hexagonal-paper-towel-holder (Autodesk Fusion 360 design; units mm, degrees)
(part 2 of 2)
sketch "Sketch2" plane through (0, 0, 5) normal (0, 0, 1) x axis (-1, 0, 0)
  line L1 (-30.6175, -23.5714) -> (-24.844, -23.5714)
  line L2 (-33.5043, -18.5714) -> (-30.6175, -23.5714)
  line L3 (-30.6175, -13.5714) -> (-33.5043, -18.5714)
  line L4 (-24.844, -13.5714) -> (-30.6175, -13.5714)
  line L5 (-21.9573, -18.5714) -> (-24.844, -13.5714)
  line L6 (-24.844, -23.5714) -> (-21.9573, -18.5714)
  line L7 (-97.4252, -100.7143) -> (-91.6517, -100.7143)
  line L8 (-100.312, -95.7143) -> (-97.4252, -100.7143)
  line L9 (-97.4252, -90.7143) -> (-100.312, -95.7143)
  line L10 (-91.6517, -90.7143) -> (-97.4252, -90.7143)
  line L11 (-88.7649, -95.7143) -> (-91.6517, -90.7143)
  line L12 (-91.6517, -100.7143) -> (-88.7649, -95.7143)
  line L13 (-36.4555, -97.1429) -> (-41.7521, -97.1429)
  line L14 (-39.2598, -102) -> (-36.4555, -97.1429)
  line L15 (-44.5564, -102) -> (-39.2598, -102)
  line L16 (-41.7521, -97.1429) -> (-44.5564, -102)
  line L17 (-55.4436, -102) -> (-58.2479, -97.1429)
  line L18 (-66.8256, -102) -> (-55.4436, -102)
  line L19 (-64.0214, -97.1429) -> (-66.8256, -102)
  line L20 (-58.2479, -97.1429) -> (-64.0214, -97.1429)
  line L21 (-77.7128, -102) -> (-80.5171, -97.1429)
  line L22 (-89.0949, -102) -> (-77.7128, -102)
  line L23 (-86.2906, -97.1429) -> (-89.0949, -102)
  line L24 (-80.5171, -97.1429) -> (-86.2906, -97.1429)
  line L25 (-99.982, -102) -> (-102.7863, -97.1429)
  line L26 (-110.9553, -102) -> (-99.982, -102)
  line L27 (-106.7432, -97.1429) -> (-110.9553, -102)
  line L28 (-102.7863, -97.1429) -> (-106.7432, -97.1429)
  line L29 (-104.2655, -94.2857) -> (-102.7863, -94.2857)
  line L30 (-99.9116, -89.2649) -> (-104.2655, -94.2857)
  line L31 (-99.8996, -89.2857) -> (-99.9116, -89.2649)
  line L32 (-102.7863, -94.2857) -> (-99.8996, -89.2857)
  line L33 (-97.931, -86.9811) -> (-97.4252, -87.8571)
  line L34 (-90.9991, -78.9875) -> (-97.931, -86.9811)
  line L35 (-88.7649, -82.8571) -> (-90.9991, -78.9875)
  line L36 (-91.6517, -87.8571) -> (-88.7649, -82.8571)
  line L37 (-97.4252, -87.8571) -> (-91.6517, -87.8571)
  line L38 (-89.0185, -76.7036) -> (-86.2906, -81.4286)
  line L39 (-84.444, -71.4286) -> (-89.0185, -76.7036)
  line L40 (-80.5171, -71.4286) -> (-84.444, -71.4286)
  line L41 (-77.6303, -76.4286) -> (-80.5171, -71.4286)
  line L42 (-80.5171, -81.4286) -> (-77.6303, -76.4286)
  line L43 (-86.2906, -81.4286) -> (-80.5171, -81.4286)
  line L44 (-25.3209, -77.8571) -> (-30.6175, -77.8571)
  line L45 (-30.856, -87.4441) -> (-25.3209, -77.8571)
  line L46 (-33.5043, -82.8571) -> (-30.856, -87.4441)
  line L47 (-30.6175, -77.8571) -> (-33.5043, -82.8571)
  line L48 (-14.1863, -58.5714) -> (-19.4829, -58.5714)
  line L49 (-19.7214, -68.1584) -> (-14.1863, -58.5714)
  line L50 (-22.3697, -63.5714) -> (-19.7214, -68.1584)
  line L51 (-19.4829, -58.5714) -> (-22.3697, -63.5714)
  line L52 (-86.2906, -94.2857) -> (-80.5171, -94.2857)
  line L53 (-89.1773, -89.2857) -> (-86.2906, -94.2857)
  line L54 (-86.2906, -84.2857) -> (-89.1773, -89.2857)
  line L55 (-80.5171, -84.2857) -> (-86.2906, -84.2857)
  line L56 (-77.6303, -89.2857) -> (-80.5171, -84.2857)
  line L57 (-80.5171, -94.2857) -> (-77.6303, -89.2857)
  line L58 (-75.156, -100.7143) -> (-69.3825, -100.7143)
  line L59 (-78.0427, -95.7143) -> (-75.156, -100.7143)
  line L60 (-75.156, -90.7143) -> (-78.0427, -95.7143)
  line L61 (-69.3825, -90.7143) -> (-75.156, -90.7143)
  line L62 (-66.4957, -95.7143) -> (-69.3825, -90.7143)
  line L63 (-69.3825, -100.7143) -> (-66.4957, -95.7143)
  line L64 (-75.156, -87.8571) -> (-69.3825, -87.8571)
  line L65 (-78.0427, -82.8571) -> (-75.156, -87.8571)
  line L66 (-75.156, -77.8571) -> (-78.0427, -82.8571)
  line L67 (-69.3825, -77.8571) -> (-75.156, -77.8571)
  line L68 (-66.4957, -82.8571) -> (-69.3825, -77.8571)
  line L69 (-69.3825, -87.8571) -> (-66.4957, -82.8571)
  line L70 (-64.0214, -94.2857) -> (-58.2479, -94.2857)
  line L71 (-66.9081, -89.2857) -> (-64.0214, -94.2857)
  line L72 (-64.0214, -84.2857) -> (-66.9081, -89.2857)
  line L73 (-58.2479, -84.2857) -> (-64.0214, -84.2857)
  line L74 (-55.3611, -89.2857) -> (-58.2479, -84.2857)
  line L75 (-58.2479, -94.2857) -> (-55.3611, -89.2857)
  line L76 (-52.8868, -100.7143) -> (-47.1132, -100.7143)
  line L77 (-55.7735, -95.7143) -> (-52.8868, -100.7143)
  line L78 (-52.8868, -90.7143) -> (-55.7735, -95.7143)
  line L79 (-47.1132, -90.7143) -> (-52.8868, -90.7143)
  line L80 (-44.2265, -95.7143) -> (-47.1132, -90.7143)
  line L81 (-47.1132, -100.7143) -> (-44.2265, -95.7143)
  line L82 (-75.156, -75) -> (-69.3825, -75)
  line L83 (-78.0427, -70) -> (-75.156, -75)
  line L84 (-75.156, -65) -> (-78.0427, -70)
  line L85 (-69.3825, -65) -> (-75.156, -65)
  line L86 (-66.4957, -70) -> (-69.3825, -65)
  line L87 (-69.3825, -75) -> (-66.4957, -70)
  line L88 (-64.0214, -81.4286) -> (-58.2479, -81.4286)
  line L89 (-66.9081, -76.4286) -> (-64.0214, -81.4286)
  line L90 (-64.0214, -71.4286) -> (-66.9081, -76.4286)
  line L91 (-58.2479, -71.4286) -> (-64.0214, -71.4286)
  line L92 (-55.3611, -76.4286) -> (-58.2479, -71.4286)
  line L93 (-58.2479, -81.4286) -> (-55.3611, -76.4286)
  line L94 (-52.8868, -87.8571) -> (-47.1132, -87.8571)
  line L95 (-55.7735, -82.8571) -> (-52.8868, -87.8571)
  line L96 (-52.8868, -77.8571) -> (-55.7735, -82.8571)
  line L97 (-47.1132, -77.8571) -> (-52.8868, -77.8571)
  line L98 (-44.2265, -82.8571) -> (-47.1132, -77.8571)
  line L99 (-47.1132, -87.8571) -> (-44.2265, -82.8571)
  line L100 (-41.7521, -94.2857) -> (-35.9786, -94.2857)
  line L101 (-44.6389, -89.2857) -> (-41.7521, -94.2857)
  line L102 (-41.7521, -84.2857) -> (-44.6389, -89.2857)
  line L103 (-35.9786, -84.2857) -> (-41.7521, -84.2857)
  line L104 (-33.0919, -89.2857) -> (-35.9786, -84.2857)
  line L105 (-35.9786, -94.2857) -> (-33.0919, -89.2857)
  line L106 (-64.0214, -68.5714) -> (-58.2479, -68.5714)
  line L107 (-66.9081, -63.5714) -> (-64.0214, -68.5714)
  line L108 (-64.0214, -58.5714) -> (-66.9081, -63.5714)
  line L109 (-58.2479, -58.5714) -> (-64.0214, -58.5714)
  line L110 (-55.3611, -63.5714) -> (-58.2479, -58.5714)
  line L111 (-58.2479, -68.5714) -> (-55.3611, -63.5714)
  line L112 (-41.7521, -81.4286) -> (-35.9786, -81.4286)
  line L113 (-44.6389, -76.4286) -> (-41.7521, -81.4286)
  line L114 (-41.7521, -71.4286) -> (-44.6389, -76.4286)
  line L115 (-35.9786, -71.4286) -> (-41.7521, -71.4286)
  line L116 (-33.0919, -76.4286) -> (-35.9786, -71.4286)
  line L117 (-35.9786, -81.4286) -> (-33.0919, -76.4286)
  line L118 (-52.8868, -62.1429) -> (-47.1132, -62.1429)
  line L119 (-55.7735, -57.1429) -> (-52.8868, -62.1429)
  line L120 (-52.8868, -52.1429) -> (-55.7735, -57.1429)
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  point P28 (-110.9553, -102)
  point P274 (-110.9553, -102)
  coincident P28 P274
extrude "Extrude2" add sketch "Sketch2" along normal blind 17 named "d15_1_1"
extrude "Extrude3" add sketch "Sketch2" along normal blind 30 named "d17_1_1"
sketch "Sketch3" plane through (-17.3205, 10, 0) normal (-0.866, 0.5, 0) x axis (-0.5, -0.866, 0)
  line L1 (0, 0) -> (-109.6966, 0)
  line L2 (0, 5) -> (0, 0)
  line L3 (-106.2324, 5) -> (0, 5)
  line L4 (-106.2324, 35) -> (-106.2324, 5)
  line L5 (-109.6966, 35) -> (-106.2324, 35)
  line L6 (-109.6966, 0) -> (-109.6966, 35)
  line L7 (-91.618, 35) -> (-106.2324, 35)
  line L8 (-94.1706, 0) -> (-109.6966, 0)
  line L9 (-106.2324, 35) -> (-94.1706, 0)
  point P6 (-106.2324, 35)
  point P8 (-106.2324, 35)
  point P10 (-94.1706, 0)
  point P2 (-109.6966, 0)
  point P11 (-109.6966, 0)
  point P12 (-106.2324, 35)
  horizontal L7
  coincident P6 P8
  coincident L1 P10
  coincident P2 P11
  coincident P6 P12
  dimension "d73_1" distance P10 P11 = 15.526
extrude "Extrude4" add sketch "Sketch3" profile of L1 L3 L4 L5 L6 against normal blind 3 named "d20_1_1"
sketch "Sketch4" plane through (15.1099, -13.1031, 0) normal (0.7555, -0.6552, 0) x axis (0.6552, 0.7555, 0)
  line L1 (156.3259, 0) -> (0, 0)
  line L2 (156.3259, 35) -> (156.3259, 0)
  line L3 (152.3549, 35) -> (156.3259, 35)
  line L4 (152.3549, 5) -> (152.3549, 35)
  line L5 (0, 5) -> (152.3549, 5)
  line L6 (0, 0) -> (0, 5)
  line L7 (168.6241, 35) -> (152.3549, 35)
  line L8 (140.7999, 0) -> (156.3259, 0)
  line L9 (152.3549, 35) -> (140.7999, 0)
  point P5 (152.3549, 35)
  point P8 (152.3549, 35)
  point P3 (156.3259, 0)
  point P10 (156.3259, 0)
  point P11 (140.7999, 0)
  horizontal L7
  coincident P5 P8
  coincident P3 P10
  perpendicular L2 L8
  dimension "d74_1" distance P10 P11 = 15.526
extrude "Extrude5" add sketch "Sketch4" profile of L4 L5 L9 against normal blind 3 named "d23_1_1"
work_plane "WorkPlane1" RotateAngle 90
sketch "Sketch7" plane through (37.5278, 105, 17.5) normal (-1, 0, 0) x axis (0, 1, 0)
  line L1 (0, -17.5) -> (0, 17.5)
  line L2 (20.5, -17.5) -> (0, -17.5)
  line L3 (20.5, 17.5) -> (20.5, -17.5)
  line L4 (0, 17.5) -> (20.5, 17.5)
  line L5 (0, -17.5) -> (0, 17.5)
  point P3 (0, -17.5)
  point P4 (0, -17.5)
  point P5 (20.5, -17.5)
  horizontal L2
  vertical L3
  horizontal L4
  vertical L5
  coincident P3 P4
  dimension "d76" distance P4 P5 = 20.5
extrude "Extrude8" add sketch "Sketch7" against normal blind 3
sketch "Sketch8" plane through (0, 125.5, 0) normal (0, 1, 0) x axis (-1, 0, 0)
  line L1 (-37.5278, 35) -> (-37.5278, 0)
  line L2 (-40.5278, 35) -> (-37.5278, 35)
  line L3 (-40.5278, 0) -> (-40.5278, 35)
  line L4 (-37.5278, 0) -> (-40.5278, 0)
  line L5 (-117.5278, 35) -> (-37.5278, 35)
  line L6 (-117.5278, 0) -> (-117.5278, 35)
  line L7 (-37.5278, 0) -> (-117.5278, 0)
  line L8 (-37.5278, 35) -> (-37.5278, 0)
  line L9 (-117.5278, 35) -> (-117.5278, 0)
  point P3 (-37.5278, 35)
  point P6 (-37.5278, 35)
  point P10 (-117.5278, 0)
  horizontal L5
  vertical L6
  horizontal L7
  vertical L8
  coincident P3 P6
  coincident L6 P10
extrude "Extrude9" add sketch "Sketch8" along normal blind 3
move "Move1"
move "Move2"
move "Move3"
move "Move4"
mirror "Mirror1" mirrorStitchTolerance 0.1 named "d39_1_1"
sketch "Sketch1" plane through (0, 0, 0) normal (0, 0, 1) x axis (1, 0, 0)
  line L1 (150, 1000) -> (-150, 1000)
  line L2 (150, -1000) -> (150, 1000)
  line L3 (-150, -1000) -> (150, -1000)
  line L4 (-150, 1000) -> (-150, -1000)
  line L5 (150, -1000) -> (-150, 1000)
  line L6 (-150, -1000) -> (150, 1000)
  point P6 (0, 0)
  point P1 (0, 0)
  point P4 (150, -1000)
  point P5 (-150, -1000)
  point P3 (150, 1000)
  horizontal L1
  perpendicular L1 L2
  parallel L1 L3
  parallel L2 L4
  coincident L5 P6
  coincident L6 P6
  coincident P1 P6
  dimension "d81" distance P4 P5 = 300
  dimension "d82" distance P3 P4 = 2000
extrude "Extrude1" new body sketch "Sketch1" profile of L1 L2 L3 L4 along normal blind 20
move "Move1"
position "Position3"
position "Position4"
position "Position5"
position "Position6"
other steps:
create_component "CreateComponent1"
create_component "CreateComponent2"
create_component "CreateComponent3"
create_component "CreateComponent4"
create_component "CreateComponent5"
create_component "CreateComponent6"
